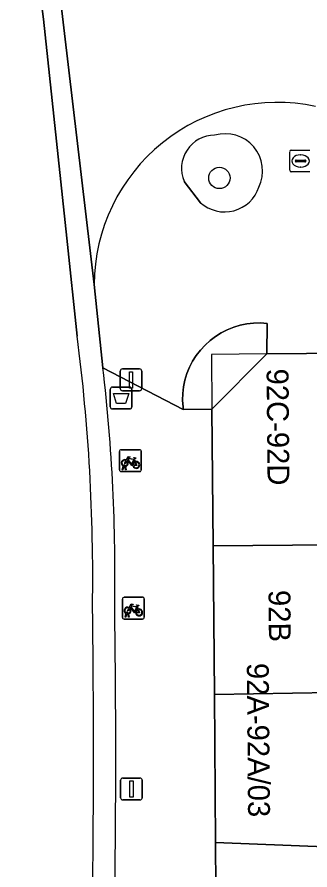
# Model space of a CAD drawing. Extents: x 160856 to 161310, y 384024 to 384878.
# Drawn here: x 161132.34 to 161145.74, y 384255.99 to 384295.05 of the extents above; entities that cross this region are included whole.
import ezdxf

# ---------------------------------------------------------------- set-up
doc = ezdxf.new("R2010")
doc.units = 0
for name, color, linetype in [('IMGEO_Afvalbak', 7, 'Continuous'), ('IMGEO_Boom', 7, 'Continuous'), ('IMGEO_Fietsenrek', 7, 'Continuous'), ('IMGEO_Fietspad_gesloten', 7, 'Continuous'), ('IMGEO_Fietspad_open', 7, 'Continuous'), ('IMGEO_Groenvoorziening', 7, 'Continuous'), ('IMGEO_Lichtmast', 7, 'Continuous'), ('IMGEO_Pand', 7, 'Continuous'), ('IMGEO_Pand_nummerreeks', 7, 'Continuous'), ('IMGEO_Pand_overbouw', 7, 'Continuous'), ('IMGEO_Rijbaan_lokaal_open', 7, 'Continuous'), ('IMGEO_Rioolput', 7, 'Continuous'), ('IMGEO_Voetpad_open', 7, 'Continuous')]:
    doc.layers.add(name, color=color, linetype=linetype)

msp = doc.modelspace()

# ---------------------------------------------------------------- linework, layer by layer
at = {"layer": 'IMGEO_Afvalbak'}
for p, q in [((161136.604, 384277.202), (161136.604, 384278.002)), ((161136.604, 384278.002), (161136.604, 384277.202)), ((161136.704, 384278.102), (161137.494, 384278.102)), ((161137.494, 384278.102), (161136.704, 384278.102)), ((161137.594, 384278.002), (161137.594, 384277.202)), ((161137.594, 384277.202), (161137.594, 384278.002)), ((161137.494, 384277.102), (161136.704, 384277.102)), ((161136.704, 384277.102), (161137.494, 384277.102))]:
    msp.add_line(p, q, dxfattribs=at)
msp.add_lwpolyline([(161136.747, 384277.816), (161137.451, 384277.816), (161137.302, 384277.346), (161136.896, 384277.346), (161136.747, 384277.816)], dxfattribs=at)
for centre, start, end in [((161136.704, 384278.002), 90, 180), ((161136.704, 384278.002), 90, 180), ((161137.494, 384278.002), 0, 90), ((161137.494, 384278.002), 360, 90), ((161136.704, 384277.202), 180, 270), ((161136.704, 384277.202), 180, 270), ((161137.494, 384277.202), 270, 0), ((161137.494, 384277.202), 270, 0)]:
    msp.add_arc(centre, 0.1, start, end, dxfattribs=at)
at = {"layer": 'IMGEO_Boom'}
msp.add_circle((161141.6, 384287.686), 0.489, dxfattribs=at)
at = {"layer": 'IMGEO_Fietsenrek'}
for p, q in [((161137.026, 384274.313), (161137.026, 384275.154)), ((161137.026, 384275.154), (161137.026, 384274.313)), ((161137.101, 384275.238), (161137.942, 384275.238)), ((161137.942, 384275.238), (161137.101, 384275.238)), ((161138.026, 384275.163), (161138.026, 384274.322)), ((161138.026, 384274.322), (161138.026, 384275.163)), ((161137.713, 384274.787), (161137.749, 384274.692)), ((161137.153, 384274.322), (161137.192, 384274.482)), ((161137.222, 384274.47), (161137.187, 384274.322)), ((161137.264, 384274.494), (161137.263, 384274.498)), ((161137.305, 384274.322), (161137.271, 384274.464)), ((161137.295, 384274.505), (161137.296, 384274.498)), ((161137.303, 384274.468), (161137.338, 384274.322)), ((161137.951, 384274.238), (161137.11, 384274.238)), ((161137.11, 384274.238), (161137.951, 384274.238)), ((161137.187, 384274.322), (161137.153, 384274.322)), ((161137.338, 384274.322), (161137.305, 384274.322)), ((161137.158, 384267.557), (161137.158, 384268.398)), ((161137.158, 384268.398), (161137.158, 384267.557)), ((161137.233, 384268.482), (161138.074, 384268.482)), ((161138.074, 384268.482), (161137.233, 384268.482)), ((161138.158, 384268.407), (161138.158, 384267.566)), ((161138.158, 384267.566), (161138.158, 384268.407)), ((161137.285, 384267.566), (161137.324, 384267.726)), ((161137.354, 384267.714), (161137.319, 384267.566)), ((161137.396, 384267.738), (161137.395, 384267.742)), ((161137.427, 384267.749), (161137.428, 384267.742)), ((161137.435, 384267.712), (161137.47, 384267.566)), ((161137.845, 384268.031), (161137.881, 384267.936)), ((161138.083, 384267.482), (161137.242, 384267.482)), ((161137.242, 384267.482), (161138.083, 384267.482)), ((161137.319, 384267.566), (161137.285, 384267.566)), ((161137.437, 384267.566), (161137.403, 384267.708)), ((161137.47, 384267.566), (161137.437, 384267.566))]:
    msp.add_line(p, q, dxfattribs=at)
for points in [[(161137.339, 384274.764), (161137.434, 384274.928), (161137.52, 384274.914), (161137.522, 384274.905), (161137.466, 384274.894), (161137.439, 384274.849), (161137.695, 384274.808)], [(161137.635, 384274.52), (161137.585, 384274.52), (161137.394, 384274.771), (161137.375, 384274.739)], [(161137.682, 384274.783), (161137.425, 384274.824), (161137.408, 384274.795), (161137.575, 384274.575), (161137.682, 384274.783)], [(161137.73, 384274.685), (161137.7, 384274.762), (161137.591, 384274.544), (161137.634, 384274.544)], [(161137.695, 384274.808), (161137.72, 384274.857), (161137.714, 384274.861), (161137.691, 384274.865), (161137.679, 384274.872), (161137.678, 384274.875), (161137.68, 384274.88), (161137.775, 384274.865), (161137.777, 384274.855), (161137.767, 384274.842), (161137.755, 384274.836), (161137.741, 384274.842), (161137.713, 384274.787)], [(161137.36, 384274.712), (161137.308, 384274.622), (161137.268, 384274.597), (161137.269, 384274.644), (161137.324, 384274.738)], [(161137.664, 384274.544), (161137.784, 384274.543), (161137.74, 384274.657)], [(161137.76, 384274.664), (161137.815, 384274.519), (161137.665, 384274.519)], [(161137.471, 384268.008), (161137.566, 384268.172), (161137.652, 384268.158), (161137.654, 384268.149), (161137.598, 384268.138), (161137.571, 384268.093), (161137.827, 384268.052)], [(161137.827, 384268.052), (161137.852, 384268.101), (161137.846, 384268.105), (161137.823, 384268.109), (161137.811, 384268.116), (161137.81, 384268.119), (161137.812, 384268.124), (161137.907, 384268.109), (161137.909, 384268.099), (161137.899, 384268.086), (161137.887, 384268.08), (161137.873, 384268.086), (161137.845, 384268.031)], [(161137.492, 384267.956), (161137.44, 384267.866), (161137.4, 384267.841), (161137.401, 384267.888), (161137.456, 384267.982)], [(161137.767, 384267.764), (161137.717, 384267.764), (161137.526, 384268.015), (161137.507, 384267.983)], [(161137.814, 384268.027), (161137.557, 384268.068), (161137.54, 384268.039), (161137.707, 384267.819), (161137.814, 384268.027)], [(161137.862, 384267.929), (161137.832, 384268.006), (161137.723, 384267.788), (161137.766, 384267.788)], [(161137.796, 384267.788), (161137.916, 384267.787), (161137.872, 384267.901)], [(161137.892, 384267.908), (161137.947, 384267.763), (161137.797, 384267.763)]]:
    msp.add_lwpolyline(points, dxfattribs=at)
for centre, radius, start, end in [((161137.104, 384275.16), 0.0779, 92.4484, 184.2845), ((161137.104, 384275.16), 0.0779, 92.4484, 184.2845), ((161137.948, 384275.16), 0.0779, 2.4484, 94.2845), ((161137.948, 384275.16), 0.0779, 2.4484, 94.2845), ((161137.266, 384274.623), 0.159, 62.6766, 242.1369), ((161137.266, 384274.623), 0.129, 63.3192, 238.903), ((161137.246, 384274.494), 0.0499, 12.8025, 158.6934), ((161137.266, 384274.623), 0.159, 253.9967, 271.7867), ((161137.246, 384274.494), 0.0174, 12.8025, 163.4502), ((161137.266, 384274.623), 0.129, 253.415, 269.0204), ((161137.266, 384274.623), 0.129, 283.6043, 43.4302), ((161137.266, 384274.623), 0.159, 283.5766, 46.6042), ((161137.793, 384274.539), 0.159, 113.3408, 178.3217), ((161137.793, 384274.539), 0.159, 187.0065, 105.7708), ((161137.793, 384274.539), 0.129, 113.923, 177.9556), ((161137.793, 384274.539), 0.129, 188.6715, 104.5883), ((161137.104, 384274.316), 0.0779, 182.4484, 274.2845), ((161137.104, 384274.316), 0.0779, 182.4484, 274.2845), ((161137.948, 384274.316), 0.0779, 272.4484, 4.2845), ((161137.948, 384274.316), 0.0779, 272.4484, 4.2845), ((161137.236, 384268.404), 0.0779, 92.4484, 184.2845), ((161137.236, 384268.404), 0.0779, 92.4484, 184.2845), ((161138.08, 384268.404), 0.0779, 2.4484, 94.2845), ((161138.08, 384268.404), 0.0779, 2.4484, 94.2845), ((161137.398, 384267.867), 0.159, 62.6766, 242.1369), ((161137.398, 384267.867), 0.129, 63.3192, 238.903), ((161137.378, 384267.738), 0.0499, 12.8025, 158.6934), ((161137.398, 384267.867), 0.159, 253.9967, 271.7867), ((161137.378, 384267.738), 0.0174, 12.8025, 163.4502), ((161137.398, 384267.867), 0.129, 253.415, 269.0204), ((161137.398, 384267.867), 0.129, 283.6043, 43.4302), ((161137.398, 384267.867), 0.159, 283.5766, 46.6042), ((161137.925, 384267.783), 0.159, 113.3408, 178.3217), ((161137.925, 384267.783), 0.159, 187.0065, 105.7708), ((161137.925, 384267.783), 0.129, 113.923, 177.9556), ((161137.925, 384267.783), 0.129, 188.6715, 104.5883), ((161137.236, 384267.56), 0.0779, 182.4484, 274.2845), ((161137.236, 384267.56), 0.0779, 182.4484, 274.2845), ((161138.08, 384267.56), 0.0779, 272.4484, 4.2845), ((161138.08, 384267.56), 0.0779, 272.4484, 4.2845)]:
    msp.add_arc(centre, radius, start, end, dxfattribs=at)
at = {"layer": 'IMGEO_Fietspad_gesloten'}
msp.add_lwpolyline([(161135.089, 384280.432), (161134.613, 384284.922), (161133.548, 384294.958), (161132.338, 384304.153)], dxfattribs=at)
for centre, radius, start, end in [((161049.82, 384269.383), 85.982, 359.1311, 7.3832), ((160657.158, 384261.351), 478.681, 358.08877, 0.80539)]:
    msp.add_arc(centre, radius, start, end, dxfattribs=at)
at = {"layer": 'IMGEO_Fietspad_open'}
for points in [[(161132.338, 384304.153), (161133.548, 384294.958), (161134.613, 384284.922), (161135.089, 384280.432)], [(161136.27, 384278.993), (161135.868, 384282.811), (161133.319, 384304.395)]]:
    msp.add_lwpolyline(points, dxfattribs=at)
for centre, radius, start, end in [((161049.82, 384269.383), 85.982, 359.1311, 7.3832), ((161054.056, 384269.465), 82.764, 358.97397, 6.61068), ((160657.158, 384261.351), 478.681, 358.08877, 0.80539), ((160683.42, 384261.325), 453.436, 357.95822, 0.84131)]:
    msp.add_arc(centre, radius, start, end, dxfattribs=at)
at = {"layer": 'IMGEO_Groenvoorziening'}
msp.add_lwpolyline([(161139.981, 384287.529), (161140.737, 384286.547)], dxfattribs=at)
for centre, radius, start, end in [((161141.392, 384288.115), 1.528, 90.3319, 202.5386), ((161141.869, 384288.003), 1.709, 334.3634, 106.5249), ((161141.838, 384287.783), 1.655, 228.2918, 341.739)]:
    msp.add_arc(centre, radius, start, end, dxfattribs=at)
at = {"layer": 'IMGEO_Lichtmast'}
for p, q in [((161137.059, 384278.035), (161137.059, 384278.835)), ((161137.059, 384278.835), (161137.059, 384278.035)), ((161137.159, 384278.935), (161137.949, 384278.935)), ((161137.949, 384278.935), (161137.159, 384278.935)), ((161138.049, 384278.835), (161138.049, 384278.035)), ((161138.049, 384278.035), (161138.049, 384278.835)), ((161137.949, 384277.935), (161137.159, 384277.935)), ((161137.159, 384277.935), (161137.949, 384277.935)), ((161137.075, 384259.297), (161137.075, 384260.097)), ((161137.075, 384260.097), (161137.075, 384259.297)), ((161137.175, 384260.197), (161137.965, 384260.197)), ((161137.965, 384260.197), (161137.175, 384260.197)), ((161138.065, 384260.097), (161138.065, 384259.297)), ((161138.065, 384259.297), (161138.065, 384260.097)), ((161137.965, 384259.197), (161137.175, 384259.197)), ((161137.175, 384259.197), (161137.965, 384259.197))]:
    msp.add_line(p, q, dxfattribs=at)
for points in [[(161137.479, 384278.81), (161137.629, 384278.81), (161137.629, 384278.06), (161137.479, 384278.06), (161137.479, 384278.81)], [(161137.495, 384260.072), (161137.645, 384260.072), (161137.645, 384259.322), (161137.495, 384259.322), (161137.495, 384260.072)]]:
    msp.add_lwpolyline(points, dxfattribs=at)
for centre, start, end in [((161137.159, 384278.835), 90, 180), ((161137.159, 384278.835), 90, 180), ((161137.949, 384278.835), 0, 90), ((161137.949, 384278.835), 360, 90), ((161137.159, 384278.035), 180, 270), ((161137.159, 384278.035), 180, 270), ((161137.949, 384278.035), 270, 0), ((161137.949, 384278.035), 270, 0), ((161137.175, 384260.097), 90, 180), ((161137.175, 384260.097), 90, 180), ((161137.965, 384260.097), 0, 90), ((161137.965, 384260.097), 360, 90), ((161137.175, 384259.297), 180, 270), ((161137.175, 384259.297), 180, 270), ((161137.965, 384259.297), 270, 0), ((161137.965, 384259.297), 270, 0)]:
    msp.add_arc(centre, 0.1, start, end, dxfattribs=at)
at = {"layer": 'IMGEO_Pand'}
for points in [[(161141.31, 384270.831), (161150.379, 384270.909), (161150.391, 384269.633), (161151.719, 384269.658), (161151.804, 384265.202), (161152.482, 384265.215), (161152.36, 384279.382), (161152.819, 384279.386), (161152.816, 384279.701), (161143.777, 384279.624), (161141.256, 384277.091)], [(161141.31, 384270.831), (161141.368, 384264.026), (161150.305, 384264.184), (161150.202, 384269.629), (161150.391, 384269.633), (161150.379, 384270.909)], [(161153.595, 384264.247), (161150.305, 384264.184), (161141.368, 384264.026), (161141.426, 384257.244), (161153.738, 384256.763)], [(161169.999, 384255.404), (161170.031, 384256.365), (161153.738, 384256.763), (161141.426, 384257.244), (161141.444, 384255.163), (161141.296, 384250.803), (161153.827, 384250.264), (161159.957, 384250), (161164.66, 384249.798), (161169.644, 384249.7), (161169.663, 384250)]]:
    msp.add_lwpolyline(points, close=True, dxfattribs=at)
at = {"layer": 'IMGEO_Pand_overbouw'}
msp.add_lwpolyline([(161141.256, 384277.091), (161143.777, 384279.624), (161141.234, 384279.602)], close=True, dxfattribs=at)
at = {"layer": 'IMGEO_Rijbaan_lokaal_open'}
msp.add_lwpolyline([(161133.319, 384304.395), (161135.868, 384282.811)], dxfattribs=at)
msp.add_arc((161144.244, 384282.768), 8.376, 77.9127, 179.7029, dxfattribs=at)
at = {"layer": 'IMGEO_Rioolput'}
for p, q in [((161144.817, 384288.036), (161144.817, 384288.888)), ((161144.892, 384288.962), (161145.744, 384288.962)), ((161145.076, 384288.456), (161145.076, 384288.468)), ((161145.514, 384288.419), (161145.116, 384288.419)), ((161145.119, 384288.505), (161145.517, 384288.505)), ((161145.305, 384288.742), (161145.33, 384288.742)), ((161145.56, 384288.468), (161145.56, 384288.456)), ((161145.328, 384288.182), (161145.303, 384288.182)), ((161145.744, 384287.962), (161144.892, 384287.962))]:
    msp.add_line(p, q, dxfattribs=at)
for points in [[(161144.817, 384288.036), (161144.817, 384288.888)], [(161144.892, 384288.962), (161145.744, 384288.962)], [(161145.744, 384287.962), (161144.892, 384287.962)]]:
    msp.add_lwpolyline(points, dxfattribs=at)
for centre, radius, start, end in [((161144.894, 384288.886), 0.0765, 91.552, 178.448), ((161144.894, 384288.886), 0.0765, 91.552, 178.448), ((161145.116, 384288.465), 0.0403, 85.8775, 175.7526), ((161145.113, 384288.455), 0.0366, 178.938, 274.7102), ((161145.517, 384288.462), 0.043, 264.8664, 352.4533), ((161145.521, 384288.467), 0.0386, 1.7309, 96.639), ((161144.894, 384288.038), 0.0765, 181.552, 268.448), ((161144.894, 384288.038), 0.0765, 181.552, 268.448)]:
    msp.add_arc(centre, radius, start, end, dxfattribs=at)
for centre, major_axis, ratio, start_param, end_param in [((161145.304, 384288.462), (-0.387, 0.002), 0.722429, 4.712389, 7.853982), ((161145.329, 384288.462), (-0.39, 0.002), 0.717154, 1.570796, 4.712389)]:
    msp.add_ellipse(centre, major_axis=major_axis, ratio=ratio, start_param=start_param, end_param=end_param, dxfattribs=at)
at = {"layer": 'IMGEO_Voetpad_open'}
for points in [[(161140.737, 384286.547), (161139.981, 384287.529)], [(161135.868, 384282.811), (161136.27, 384278.993), (161139.948, 384277.078), (161139.934, 384277.189), (161139.915, 384277.5), (161139.924, 384277.812), (161139.96, 384278.121), (161140.024, 384278.426), (161140.115, 384278.725), (161140.232, 384279.013), (161140.375, 384279.29), (161140.542, 384279.554), (161140.731, 384279.801), (161140.942, 384280.031), (161141.173, 384280.24), (161141.421, 384280.429), (161141.685, 384280.594), (161141.963, 384280.735), (161142.253, 384280.851), (161142.551, 384280.94), (161142.857, 384281.002), (161143.166, 384281.037), (161143.478, 384281.044), (161143.789, 384281.023), (161143.777, 384279.624), (161152.816, 384279.701)], [(161135.206, 384182.519), (161137.747, 384203.691), (161137.796, 384204.099), (161137.866, 384204.68), (161138.763, 384212.161), (161139.413, 384217.573), (161140.22, 384224.296), (161140.565, 384227.17), (161140.67, 384230.878), (161140.869, 384237.95), (161140.916, 384239.606), (161141.077, 384244.333), (161141.269, 384250), (161141.296, 384250.803), (161141.444, 384255.163), (161141.426, 384257.244), (161141.368, 384264.026), (161141.31, 384270.831), (161141.256, 384277.091), (161139.948, 384277.078), (161136.27, 384278.993)]]:
    msp.add_lwpolyline(points, dxfattribs=at)
msp.add_lwpolyline([(161141.256, 384277.091), (161143.777, 384279.624), (161143.789, 384281.023), (161143.478, 384281.044), (161143.166, 384281.037), (161142.857, 384281.002), (161142.551, 384280.94), (161142.253, 384280.851), (161141.963, 384280.735), (161141.685, 384280.594), (161141.421, 384280.429), (161141.173, 384280.24), (161140.942, 384280.031), (161140.731, 384279.801), (161140.542, 384279.554), (161140.375, 384279.29), (161140.232, 384279.013), (161140.115, 384278.725), (161140.024, 384278.426), (161139.96, 384278.121), (161139.924, 384277.812), (161139.915, 384277.5), (161139.934, 384277.189), (161139.948, 384277.078)], close=True, dxfattribs=at)
for centre, radius, start, end in [((161144.244, 384282.768), 8.376, 77.9127, 179.7029), ((161141.392, 384288.115), 1.528, 90.3319, 202.5386), ((161141.869, 384288.003), 1.709, 334.3634, 106.5249), ((161141.838, 384287.783), 1.655, 228.2918, 341.739), ((161054.056, 384269.465), 82.764, 358.97397, 6.61068), ((160683.42, 384261.325), 453.436, 357.95822, 0.84131)]:
    msp.add_arc(centre, radius, start, end, dxfattribs=at)

# ---------------------------------------------------------------- texts
at = {"layer": 'IMGEO_Pand_nummerreeks'}
for s, rotation, p in [('92C-92D', 270.4912, (161143.76, 384278.948)), ('92B', 270.4912, (161143.847, 384268.806)), ('92A-92A/03', 270.4925, (161142.855, 384265.465))]:
    msp.add_text(s, height=1, rotation=rotation, dxfattribs=at).set_placement(p)

doc.saveas('drawing.dxf')
